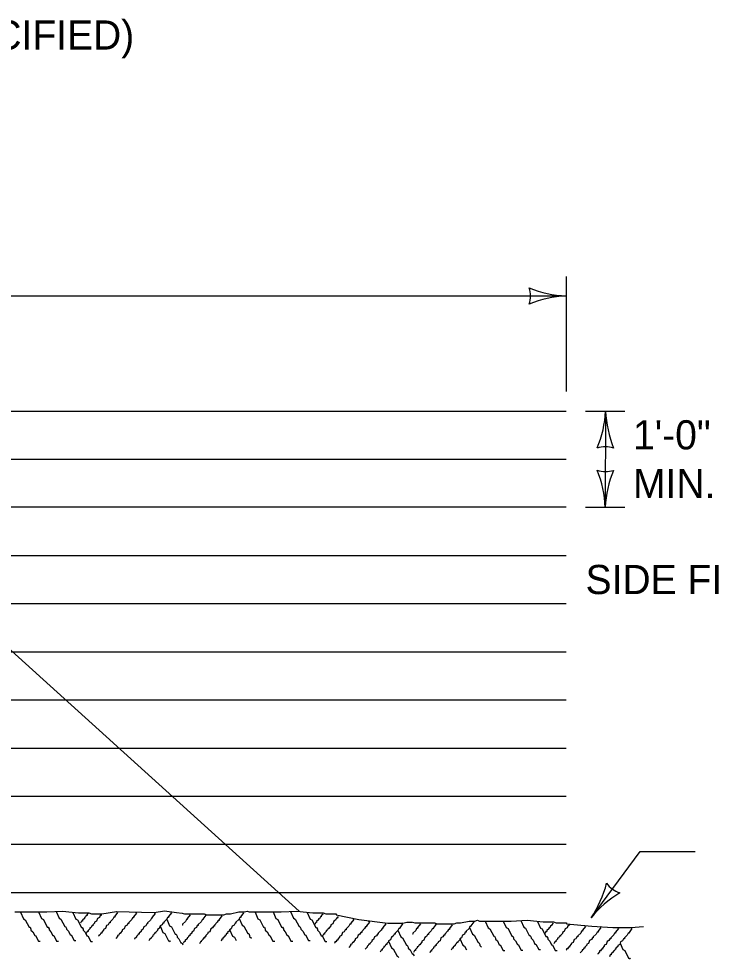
# Model space of a CAD drawing. Extents: x 49991.4 to 50021, y 49987.6 to 50011.4.
# Drawn here: x 50015.211 to 50016.641, y 50002.062 to 50003.996 of the extents above; entities that cross this region are included whole.
import ezdxf

# ---------------------------------------------------------------- set-up
doc = ezdxf.new("R2010")
doc.units = 0
for name, color, linetype in [('Level 1', 7, 'Continuous'), ('Level 2', 7, 'Continuous'), ('Level 3', 7, 'Continuous')]:
    doc.layers.add(name, color=color, linetype=linetype)

msp = doc.modelspace()

# ---------------------------------------------------------------- linework, layer by layer
at = {"layer": 'Level 1'}
for p, q in [((50015.7875, 50002.1608), (50014.1088, 50003.6812)), ((50013.737, 50003.1896), (50016.3368, 50003.1896)), ((50013.737, 50003.0906), (50016.3368, 50003.0906)), ((50016.3368, 50002.9916), (50013.737, 50002.9916)), ((50013.737, 50002.8926), (50016.3368, 50002.8926)), ((50013.737, 50002.7936), (50016.3368, 50002.7936)), ((50014.133, 50002.6946), (50016.3368, 50002.6946)), ((50014.133, 50002.5956), (50016.3368, 50002.5956)), ((50014.133, 50002.4966), (50016.3368, 50002.4966)), ((50014.3288, 50002.3976), (50016.3368, 50002.3976)), ((50014.4666, 50002.2986), (50016.3368, 50002.2986)), ((50014.6037, 50002.1996), (50016.3368, 50002.1996))]:
    msp.add_line(p, q, dxfattribs=at)
for points in [[(50015.203, 50002.1594), (50015.2628, 50002.1594), (50015.2686, 50002.1594), (50015.3014, 50002.1613), (50015.3341, 50002.1575), (50015.3554, 50002.1575), (50015.3611, 50002.1555), (50015.3746, 50002.1555), (50015.3823, 50002.1555), (50015.4125, 50002.1602), (50015.4897, 50002.158), (50015.511, 50002.1616), (50015.5354, 50002.158), (50015.5471, 50002.1567), (50015.5495, 50002.1561)], [(50015.5471, 50002.1567), (50015.5519, 50002.1555), (50015.5924, 50002.1555), (50015.5982, 50002.1536), (50015.6329, 50002.1536), (50015.6387, 50002.1555), (50015.6464, 50002.1555), (50015.6637, 50002.1594), (50015.6753, 50002.1594), (50015.6811, 50002.1613), (50015.685, 50002.1594), (50015.7447, 50002.1594), (50015.7505, 50002.1594), (50015.7833, 50002.1613), (50015.8161, 50002.1575), (50015.8373, 50002.1575), (50015.843, 50002.1555), (50015.8565, 50002.1555), (50015.8642, 50002.1555), (50015.8642, 50002.1536), (50015.9105, 50002.144), (50015.9703, 50002.1363), (50016.0011, 50002.1363), (50016.0089, 50002.1382), (50016.0204, 50002.1382)], [(50015.2151, 50002.1589), (50015.2208, 50002.1454), (50015.2247, 50002.1435), (50015.2324, 50002.128), (50015.2344, 50002.128), (50015.2362, 50002.1242), (50015.2362, 50002.1223), (50015.2401, 50002.1184), (50015.244, 50002.1107), (50015.2459, 50002.1107), (50015.2517, 50002.0991), (50015.2555, 50002.0991)], [(50015.2521, 50002.1594), (50015.2579, 50002.1459), (50015.2618, 50002.144), (50015.2695, 50002.1285), (50015.2714, 50002.1285), (50015.2734, 50002.1247), (50015.2734, 50002.1228), (50015.2772, 50002.1189), (50015.2811, 50002.1112), (50015.283, 50002.1112), (50015.2888, 50002.0996), (50015.2927, 50002.0996)], [(50015.2883, 50002.1603), (50015.2941, 50002.1469), (50015.2979, 50002.1449), (50015.3057, 50002.1295), (50015.3076, 50002.1295), (50015.3095, 50002.1257), (50015.3095, 50002.1238), (50015.3134, 50002.1199), (50015.3172, 50002.1121), (50015.3192, 50002.1121), (50015.3249, 50002.1006), (50015.3288, 50002.1006)], [(50015.3225, 50002.1584), (50015.3283, 50002.1449), (50015.3322, 50002.143), (50015.3399, 50002.1276), (50015.3418, 50002.1276), (50015.3438, 50002.1238), (50015.3438, 50002.1218), (50015.3476, 50002.1179), (50015.3515, 50002.1102), (50015.3534, 50002.1102), (50015.3592, 50002.0986), (50015.363, 50002.0986)], [(50015.3554, 50002.1575), (50015.3519, 50002.154), (50015.3519, 50002.1521), (50015.3499, 50002.1521), (50015.348, 50002.1482), (50015.3461, 50002.1482), (50015.3461, 50002.1463), (50015.3422, 50002.1424), (50015.3422, 50002.1405), (50015.3403, 50002.1405), (50015.3384, 50002.1366)], [(50015.3823, 50002.1555), (50015.3807, 50002.1539), (50015.3807, 50002.152), (50015.3788, 50002.152), (50015.3769, 50002.1482), (50015.373, 50002.1462), (50015.3711, 50002.1404), (50015.3672, 50002.1385), (50015.3672, 50002.1366), (50015.3633, 50002.1327), (50015.3633, 50002.1308), (50015.3614, 50002.1308), (50015.3595, 50002.127), (50015.3576, 50002.127), (50015.3576, 50002.125), (50015.3537, 50002.1212), (50015.3537, 50002.1192), (50015.3518, 50002.1192), (50015.3499, 50002.1153)], [(50015.4125, 50002.1602), (50015.4145, 50002.1583), (50015.4087, 50002.1506), (50015.4087, 50002.1487), (50015.4068, 50002.1487), (50015.4048, 50002.1448), (50015.3991, 50002.139), (50015.3991, 50002.1371), (50015.3971, 50002.1371), (50015.3952, 50002.1332), (50015.3914, 50002.1313), (50015.3894, 50002.1255), (50015.3855, 50002.1236), (50015.3855, 50002.1217), (50015.3817, 50002.1178), (50015.3817, 50002.1159), (50015.3798, 50002.1159), (50015.3778, 50002.112), (50015.3759, 50002.112), (50015.3759, 50002.1101), (50015.3753, 50002.1095)], [(50015.4511, 50002.1591), (50015.4531, 50002.1571), (50015.4473, 50002.1495), (50015.4473, 50002.1475), (50015.4454, 50002.1475), (50015.4434, 50002.1437), (50015.4376, 50002.1379), (50015.4376, 50002.136), (50015.4357, 50002.136), (50015.4338, 50002.1321), (50015.4299, 50002.1302), (50015.428, 50002.1244), (50015.4241, 50002.1225), (50015.4241, 50002.1206), (50015.4203, 50002.1167), (50015.4203, 50002.1148), (50015.4184, 50002.1148), (50015.4164, 50002.1109), (50015.4145, 50002.1109), (50015.4145, 50002.109), (50015.4106, 50002.1051)], [(50015.4897, 50002.158), (50015.4916, 50002.1561), (50015.4858, 50002.1484), (50015.4858, 50002.1464), (50015.4839, 50002.1464), (50015.482, 50002.1426), (50015.4762, 50002.1368), (50015.4762, 50002.1349), (50015.4743, 50002.1349), (50015.4723, 50002.131), (50015.4685, 50002.1291), (50015.4666, 50002.1233), (50015.4627, 50002.1214), (50015.4627, 50002.1194), (50015.4588, 50002.1156), (50015.4588, 50002.1137), (50015.4569, 50002.1137), (50015.455, 50002.1098), (50015.4531, 50002.1098), (50015.4531, 50002.1079), (50015.4492, 50002.104), (50015.4492, 50002.1033)], [(50015.5232, 50002.1598), (50015.5252, 50002.1579), (50015.5194, 50002.1502), (50015.5194, 50002.1482), (50015.5174, 50002.1482), (50015.5155, 50002.1444), (50015.5097, 50002.1386), (50015.5097, 50002.1367), (50015.5078, 50002.1367), (50015.5059, 50002.1328), (50015.502, 50002.1309), (50015.5001, 50002.1251), (50015.4963, 50002.1232), (50015.4963, 50002.1212), (50015.4924, 50002.1174), (50015.4924, 50002.1155), (50015.4905, 50002.1155), (50015.4885, 50002.1116), (50015.4866, 50002.1116), (50015.4866, 50002.1097), (50015.4828, 50002.1058), (50015.4828, 50002.1039), (50015.4808, 50002.1039), (50015.4789, 50002.1)], [(50015.5155, 50002.1444), (50015.5213, 50002.1309), (50015.5252, 50002.1289), (50015.5329, 50002.1135), (50015.5348, 50002.1135), (50015.5367, 50002.1096), (50015.5367, 50002.1077), (50015.5406, 50002.1039), (50015.5444, 50002.0962), (50015.5464, 50002.0962), (50015.5485, 50002.0918)], [(50015.5616, 50002.1555), (50015.5635, 50002.1536), (50015.5577, 50002.1459), (50015.5577, 50002.144), (50015.5558, 50002.144), (50015.5538, 50002.1401), (50015.5481, 50002.1344), (50015.5481, 50002.1324), (50015.5471, 50002.1324)], [(50015.5939, 50002.1546), (50015.5958, 50002.1527), (50015.59, 50002.1449), (50015.59, 50002.143), (50015.5881, 50002.143), (50015.5861, 50002.1392), (50015.5804, 50002.1334), (50015.5804, 50002.1314), (50015.5784, 50002.1314), (50015.5765, 50002.1276), (50015.5726, 50002.1257), (50015.5707, 50002.1199), (50015.5668, 50002.1179), (50015.5668, 50002.116), (50015.563, 50002.1121), (50015.563, 50002.1102), (50015.5611, 50002.1102), (50015.5592, 50002.1064), (50015.5572, 50002.1064), (50015.5572, 50002.1044), (50015.5533, 50002.1006), (50015.5533, 50002.0986), (50015.5514, 50002.0986), (50015.5495, 50002.0948)], [(50015.6271, 50002.1536), (50015.629, 50002.1517), (50015.6232, 50002.144), (50015.6232, 50002.142), (50015.6213, 50002.142), (50015.6194, 50002.1382), (50015.6136, 50002.1324), (50015.6136, 50002.1305), (50015.6117, 50002.1305), (50015.6097, 50002.1266), (50015.6059, 50002.1247), (50015.604, 50002.1189), (50015.6001, 50002.117), (50015.6001, 50002.1151), (50015.5962, 50002.1112), (50015.5962, 50002.1093), (50015.5943, 50002.1093), (50015.5924, 50002.1054), (50015.5905, 50002.1054), (50015.5905, 50002.1035), (50015.5866, 50002.0996), (50015.5866, 50002.0977), (50015.5846, 50002.0977), (50015.5827, 50002.0938)], [(50015.6714, 50002.1594), (50015.6734, 50002.1574), (50015.6676, 50002.1498), (50015.6676, 50002.1478), (50015.6656, 50002.1478), (50015.6637, 50002.144), (50015.6579, 50002.1382), (50015.6579, 50002.1363), (50015.656, 50002.1363), (50015.6541, 50002.1324), (50015.6502, 50002.1305), (50015.6483, 50002.1247), (50015.6444, 50002.1228), (50015.6444, 50002.1209), (50015.6406, 50002.117), (50015.6406, 50002.1151), (50015.6387, 50002.1151), (50015.6367, 50002.1112), (50015.6348, 50002.1112), (50015.6348, 50002.1093), (50015.631, 50002.1054), (50015.631, 50002.1035), (50015.629, 50002.1035), (50015.6271, 50002.0996)], [(50015.6647, 50002.1459), (50015.6705, 50002.1324), (50015.6743, 50002.1305), (50015.682, 50002.1151), (50015.684, 50002.1151), (50015.6859, 50002.1112), (50015.6859, 50002.1093), (50015.6895, 50002.1057)], [(50015.697, 50002.1589), (50015.7028, 50002.1454), (50015.7066, 50002.1435), (50015.7143, 50002.128), (50015.7163, 50002.128), (50015.7182, 50002.1242), (50015.7182, 50002.1223), (50015.722, 50002.1184), (50015.7259, 50002.1107), (50015.7278, 50002.1107), (50015.7336, 50002.0991), (50015.7375, 50002.0991)], [(50015.7341, 50002.1594), (50015.7399, 50002.1459), (50015.7437, 50002.144), (50015.7514, 50002.1285), (50015.7534, 50002.1285), (50015.7553, 50002.1247), (50015.7553, 50002.1228), (50015.7592, 50002.1189), (50015.763, 50002.1112), (50015.7649, 50002.1112), (50015.7707, 50002.0996), (50015.7746, 50002.0996)], [(50015.7703, 50002.1603), (50015.776, 50002.1469), (50015.7799, 50002.1449), (50015.7876, 50002.1295), (50015.7895, 50002.1295), (50015.7914, 50002.1257), (50015.7914, 50002.1238), (50015.7953, 50002.1199), (50015.7992, 50002.1121), (50015.8011, 50002.1121), (50015.8069, 50002.1006), (50015.8107, 50002.1006)], [(50015.8045, 50002.1584), (50015.8102, 50002.1449), (50015.8141, 50002.143), (50015.8218, 50002.1276), (50015.8237, 50002.1276), (50015.8257, 50002.1238), (50015.8257, 50002.1218), (50015.8296, 50002.1179), (50015.8334, 50002.1102), (50015.8353, 50002.1102), (50015.8411, 50002.0986), (50015.845, 50002.0986)], [(50015.8369, 50002.1547), (50015.8334, 50002.1512), (50015.8334, 50002.1493), (50015.8314, 50002.1493), (50015.8296, 50002.1454), (50015.8276, 50002.1454), (50015.8276, 50002.1435), (50015.8237, 50002.1397), (50015.8237, 50002.1377), (50015.8218, 50002.1377), (50015.8199, 50002.1339)], [(50015.8682, 50002.1499), (50015.8666, 50002.1483), (50015.8666, 50002.1464), (50015.8647, 50002.1464), (50015.8628, 50002.1426), (50015.859, 50002.1406), (50015.857, 50002.1348), (50015.8531, 50002.1329), (50015.8531, 50002.131), (50015.8493, 50002.1271), (50015.8493, 50002.1252), (50015.8474, 50002.1252), (50015.8454, 50002.1213), (50015.8435, 50002.1213), (50015.8435, 50002.1194), (50015.8397, 50002.1155), (50015.8397, 50002.1136), (50015.8377, 50002.1136), (50015.8358, 50002.1097)], [(50015.898, 50002.1459), (50015.8999, 50002.144), (50015.8941, 50002.1363), (50015.8941, 50002.1344), (50015.8922, 50002.1344), (50015.8902, 50002.1305), (50015.8845, 50002.1247), (50015.8845, 50002.1228), (50015.8825, 50002.1228), (50015.8806, 50002.1189), (50015.8768, 50002.117), (50015.8748, 50002.1112), (50015.871, 50002.1093), (50015.871, 50002.1073), (50015.8671, 50002.1035), (50015.8671, 50002.1016), (50015.8652, 50002.1016), (50015.8632, 50002.0977), (50015.8614, 50002.0977), (50015.8614, 50002.0958), (50015.8607, 50002.0952)], [(50016.0206, 50002.1381), (50016.0254, 50002.1369), (50016.0659, 50002.1369), (50016.0717, 50002.135), (50016.1065, 50002.135), (50016.1122, 50002.1369), (50016.1199, 50002.1369), (50016.1373, 50002.1408), (50016.1488, 50002.1408), (50016.1546, 50002.1427), (50016.1585, 50002.1408), (50016.2182, 50002.1408), (50016.224, 50002.1408), (50016.2568, 50002.1427), (50016.2896, 50002.1389), (50016.3108, 50002.1389), (50016.3165, 50002.1369), (50016.3301, 50002.1369), (50016.3377, 50002.1369), (50016.3377, 50002.135), (50016.3896, 50002.1303), (50016.433, 50002.1277), (50016.4517, 50002.1274), (50016.4701, 50002.1272), (50016.4959, 50002.1298)], [(50016.2438, 50002.1417), (50016.2495, 50002.1282), (50016.2534, 50002.1263), (50016.2611, 50002.1109), (50016.263, 50002.1109), (50016.265, 50002.1071), (50016.265, 50002.1052), (50016.2688, 50002.1013), (50016.2727, 50002.0935), (50016.2747, 50002.0935), (50016.2804, 50002.082), (50016.2843, 50002.082)], [(50015.502, 50002.1309), (50015.5078, 50002.1174), (50015.5117, 50002.1154), (50015.5194, 50002.1), (50015.5213, 50002.1), (50015.5224, 50002.0978)], [(50015.6449, 50002.1232), (50015.6507, 50002.1097), (50015.6546, 50002.1078), (50015.6583, 50002.1004)], [(50015.9303, 50002.1406), (50015.9322, 50002.1386), (50015.9264, 50002.131), (50015.9264, 50002.129), (50015.9245, 50002.129), (50015.9225, 50002.1252), (50015.9168, 50002.1194), (50015.9168, 50002.1174), (50015.9149, 50002.1174), (50015.9129, 50002.1136), (50015.909, 50002.1117), (50015.9071, 50002.1059), (50015.9033, 50002.104), (50015.9033, 50002.102), (50015.8994, 50002.0981), (50015.8994, 50002.0963), (50015.8975, 50002.0963), (50015.8955, 50002.0924), (50015.8936, 50002.0924), (50015.8936, 50002.0905), (50015.8897, 50002.0866)], [(50015.964, 50002.1372), (50015.9659, 50002.1353), (50015.9601, 50002.1276), (50015.9601, 50002.1257), (50015.9582, 50002.1257), (50015.9563, 50002.1218), (50015.9505, 50002.116), (50015.9505, 50002.1141), (50015.9486, 50002.1141), (50015.9466, 50002.1102), (50015.9428, 50002.1083), (50015.9408, 50002.1025), (50015.937, 50002.1006), (50015.937, 50002.0986), (50015.9331, 50002.0948), (50015.9331, 50002.0929), (50015.9312, 50002.0929), (50015.9293, 50002.089), (50015.9274, 50002.089), (50015.9274, 50002.0871), (50015.9235, 50002.0832), (50015.9235, 50002.0826)], [(50015.9987, 50002.1368), (50016.0006, 50002.1348), (50015.9949, 50002.1271), (50015.9949, 50002.1252), (50015.9929, 50002.1252), (50015.991, 50002.1213), (50015.9852, 50002.1155), (50015.9852, 50002.1136), (50015.9833, 50002.1136), (50015.9813, 50002.1097), (50015.9775, 50002.1078), (50015.9756, 50002.102), (50015.9717, 50002.1001), (50015.9717, 50002.0981), (50015.9679, 50002.0943), (50015.9679, 50002.0924), (50015.9659, 50002.0924), (50015.964, 50002.0885), (50015.9621, 50002.0885), (50015.9621, 50002.0866), (50015.9582, 50002.0827), (50015.9582, 50002.0808), (50015.9563, 50002.0808), (50015.9544, 50002.077)], [(50016.0351, 50002.1369), (50016.037, 50002.135), (50016.0312, 50002.1273), (50016.0312, 50002.1254), (50016.0293, 50002.1254), (50016.0274, 50002.1215), (50016.0216, 50002.1158), (50016.0216, 50002.1138), (50016.0206, 50002.1138)], [(50016.0674, 50002.136), (50016.0693, 50002.1341), (50016.0635, 50002.1263), (50016.0635, 50002.1244), (50016.0616, 50002.1244), (50016.0596, 50002.1206), (50016.0539, 50002.1148), (50016.0539, 50002.1128), (50016.052, 50002.1128), (50016.05, 50002.109), (50016.0462, 50002.1071), (50016.0442, 50002.1013), (50016.0403, 50002.0993), (50016.0403, 50002.0974), (50016.0365, 50002.0935), (50016.0365, 50002.0916), (50016.0346, 50002.0916), (50016.0327, 50002.0878), (50016.0307, 50002.0878), (50016.0307, 50002.0858), (50016.0269, 50002.082), (50016.0269, 50002.08), (50016.0249, 50002.08), (50016.023, 50002.0762)], [(50016.1006, 50002.135), (50016.1025, 50002.1331), (50016.0967, 50002.1254), (50016.0967, 50002.1234), (50016.0948, 50002.1234), (50016.0929, 50002.1196), (50016.0871, 50002.1138), (50016.0871, 50002.1118), (50016.0852, 50002.1118), (50016.0832, 50002.108), (50016.0794, 50002.1061), (50016.0775, 50002.1003), (50016.0736, 50002.0983), (50016.0736, 50002.0964), (50016.0697, 50002.0926), (50016.0697, 50002.0907), (50016.0678, 50002.0907), (50016.0659, 50002.0868), (50016.064, 50002.0868), (50016.064, 50002.0849), (50016.0601, 50002.081), (50016.0601, 50002.0791), (50016.0582, 50002.0791), (50016.0563, 50002.0752)], [(50016.145, 50002.1408), (50016.1469, 50002.1388), (50016.1411, 50002.1312), (50016.1411, 50002.1292), (50016.1391, 50002.1292), (50016.1372, 50002.1254), (50016.1315, 50002.1196), (50016.1315, 50002.1176), (50016.1295, 50002.1176), (50016.1276, 50002.1138), (50016.1237, 50002.1118), (50016.1218, 50002.1061), (50016.118, 50002.1042), (50016.118, 50002.1022), (50016.1141, 50002.0983), (50016.1141, 50002.0965), (50016.1122, 50002.0965), (50016.1102, 50002.0926), (50016.1083, 50002.0926), (50016.1083, 50002.0907), (50016.1045, 50002.0868), (50016.1045, 50002.0849), (50016.1025, 50002.0849), (50016.1006, 50002.081)], [(50016.1382, 50002.1273), (50016.144, 50002.1138), (50016.1478, 50002.1118), (50016.1556, 50002.0964), (50016.1575, 50002.0964), (50016.1594, 50002.0926), (50016.1594, 50002.0907), (50016.163, 50002.0871)], [(50016.1705, 50002.1403), (50016.1763, 50002.1268), (50016.1801, 50002.1249), (50016.1878, 50002.1094), (50016.1898, 50002.1094), (50016.1917, 50002.1056), (50016.1917, 50002.1037), (50016.1956, 50002.0998), (50016.1994, 50002.0921), (50016.2014, 50002.0921), (50016.2071, 50002.0805), (50016.211, 50002.0805)], [(50016.2076, 50002.1408), (50016.2134, 50002.1273), (50016.2173, 50002.1254), (50016.225, 50002.1099), (50016.2269, 50002.1099), (50016.2288, 50002.1061), (50016.2288, 50002.1042), (50016.2327, 50002.1003), (50016.2365, 50002.0926), (50016.2384, 50002.0926), (50016.2443, 50002.081), (50016.2481, 50002.081)], [(50016.278, 50002.1398), (50016.2838, 50002.1263), (50016.2876, 50002.1244), (50016.2953, 50002.109), (50016.2972, 50002.109), (50016.2992, 50002.1052), (50016.2992, 50002.1032), (50016.3031, 50002.0993), (50016.3069, 50002.0916), (50016.3088, 50002.0916), (50016.3146, 50002.08), (50016.3185, 50002.08)], [(50016.3104, 50002.1361), (50016.3069, 50002.1326), (50016.3069, 50002.1307), (50016.3049, 50002.1307), (50016.3031, 50002.1268), (50016.3011, 50002.1268), (50016.3011, 50002.1249), (50016.2972, 50002.1211), (50016.2972, 50002.1191), (50016.2953, 50002.1191), (50016.2934, 50002.1153)], [(50016.3441, 50002.1342), (50016.3425, 50002.1325), (50016.3425, 50002.1306), (50016.3406, 50002.1306), (50016.3387, 50002.1268), (50016.3349, 50002.1248), (50016.3329, 50002.119), (50016.329, 50002.1171), (50016.329, 50002.1152), (50016.3252, 50002.1113), (50016.3252, 50002.1094), (50016.3233, 50002.1094), (50016.3213, 50002.1056), (50016.3194, 50002.1056), (50016.3194, 50002.1036), (50016.3156, 50002.0998), (50016.3156, 50002.0979), (50016.3136, 50002.0979), (50016.3117, 50002.094)], [(50016.3744, 50002.1315), (50016.3763, 50002.1295), (50016.3705, 50002.1218), (50016.3705, 50002.1199), (50016.3686, 50002.1199), (50016.3667, 50002.116), (50016.3609, 50002.1102), (50016.3609, 50002.1083), (50016.359, 50002.1083), (50016.3571, 50002.1045), (50016.3532, 50002.1025), (50016.3513, 50002.0968), (50016.3474, 50002.0948), (50016.3474, 50002.0929), (50016.3435, 50002.0891), (50016.3435, 50002.0872), (50016.3416, 50002.0872), (50016.3397, 50002.0833), (50016.3378, 50002.0833), (50016.3378, 50002.0813), (50016.3372, 50002.0807)], [(50016.4062, 50002.1295), (50016.4082, 50002.1276), (50016.4024, 50002.1199), (50016.4024, 50002.118), (50016.4004, 50002.118), (50016.3985, 50002.1141), (50016.3927, 50002.1083), (50016.3927, 50002.1064), (50016.3908, 50002.1064), (50016.3889, 50002.1026), (50016.385, 50002.1006), (50016.383, 50002.0948), (50016.3792, 50002.0929), (50016.3792, 50002.091), (50016.3754, 50002.0871), (50016.3754, 50002.0852), (50016.3734, 50002.0852), (50016.3715, 50002.0813), (50016.3696, 50002.0813), (50016.3696, 50002.0794), (50016.3657, 50002.0755)], [(50016.4423, 50002.1276), (50016.4442, 50002.1257), (50016.4384, 50002.1179), (50016.4384, 50002.116), (50016.4365, 50002.116), (50016.4346, 50002.1121), (50016.4288, 50002.1064), (50016.4288, 50002.1044), (50016.4269, 50002.1044), (50016.4249, 50002.1006), (50016.4211, 50002.0987), (50016.4192, 50002.0928), (50016.4153, 50002.0909), (50016.4153, 50002.089), (50016.4114, 50002.0852), (50016.4114, 50002.0832), (50016.4095, 50002.0832), (50016.4076, 50002.0794), (50016.4057, 50002.0794), (50016.4057, 50002.0774), (50016.4018, 50002.0736), (50016.4018, 50002.0729)], [(50016.4701, 50002.1272), (50016.472, 50002.1252), (50016.4663, 50002.1175), (50016.4663, 50002.1156), (50016.4643, 50002.1156), (50016.4624, 50002.1117), (50016.4566, 50002.106), (50016.4566, 50002.1041), (50016.4547, 50002.1041), (50016.4528, 50002.1002), (50016.4489, 50002.0983), (50016.447, 50002.0925), (50016.4431, 50002.0906), (50016.4431, 50002.0886), (50016.4393, 50002.0848), (50016.4393, 50002.0828), (50016.4374, 50002.0828), (50016.4354, 50002.079), (50016.4335, 50002.079), (50016.4335, 50002.077), (50016.4296, 50002.0732), (50016.4296, 50002.0713), (50016.4277, 50002.0713), (50016.4258, 50002.0674)], [(50015.991, 50002.1218), (50015.9968, 50002.1083), (50016.0006, 50002.1064), (50016.0083, 50002.0909), (50016.0102, 50002.0909), (50016.0122, 50002.0871), (50016.0122, 50002.0852), (50016.016, 50002.0813), (50016.0199, 50002.0736), (50016.0218, 50002.0736), (50016.024, 50002.0692)], [(50016.1184, 50002.1046), (50016.1242, 50002.0911), (50016.1281, 50002.0892), (50016.1318, 50002.0818)], [(50015.9717, 50002.0991), (50015.9775, 50002.0856), (50015.9814, 50002.0837), (50015.9891, 50002.0683), (50015.991, 50002.0683), (50015.9921, 50002.0661)], [(50016.448, 50002.0954), (50016.4537, 50002.0819), (50016.4576, 50002.0799), (50016.4653, 50002.0645), (50016.4673, 50002.0645), (50016.4683, 50002.0623)]]:
    msp.add_lwpolyline(points, dxfattribs=at)
at = {"layer": 'Level 3'}
for p, q in [((50016.3368, 50003.4663), (50016.3368, 50003.2296)), ((50013.697, 50003.4263), (50016.3368, 50003.4263)), ((50016.3768, 50003.1896), (50016.4578, 50003.1896)), ((50016.4178, 50003.1896), (50016.4173, 50002.9916)), ((50016.3768, 50002.9916), (50016.4578, 50002.9916)), ((50016.3882, 50002.1476), (50016.4892, 50002.2835)), ((50016.4892, 50002.2835), (50016.6021, 50002.2835))]:
    msp.add_line(p, q, dxfattribs=at)
for centre, radius, start, end in [((50016.346, 50003.6484), 0.2223, 247.456, 267.6395), ((50016.2086, 50003.4263), 0.0548, 342.1388, 17.8612), ((50016.3483, 50003.1936), 0.233, 92.8273, 112.0772), ((50016.1957, 50003.1993), 0.2223, 337.3113, 357.4948), ((50016.6506, 50003.2005), 0.233, 182.6826, 201.9325), ((50016.4175, 50003.0613), 0.0548, 71.9941, 107.7165), ((50016.4177, 50003.1198), 0.0548, 251.9941, 287.7165), ((50016.1846, 50002.9806), 0.233, 2.6826, 21.9325), ((50016.6394, 50002.9818), 0.2223, 157.3113, 177.4948), ((50016.1946, 50002.2773), 0.233, 326.1809, 345.4308), ((50016.4647, 50002.2505), 0.0548, 215.4925, 251.2148), ((50016.5609, 50002.0077), 0.2223, 120.8096, 140.9932)]:
    msp.add_arc(centre, radius, start, end, dxfattribs=at)

# ---------------------------------------------------------------- texts
at = {"layer": 'Level 2'}
for s, p in [('SPECIAL BACKFILL (WHEN SPECIFIED)', (50013.9417, 50003.9329)), ('1\'-0" [305]', (50016.4744, 50003.1106)), ('MIN.', (50016.4744, 50003.0106)), ('SIDE FILL', (50016.3768, 50002.8131))]:
    msp.add_text(s, height=0.06, dxfattribs=at).set_placement(p)

doc.saveas('drawing.dxf')
